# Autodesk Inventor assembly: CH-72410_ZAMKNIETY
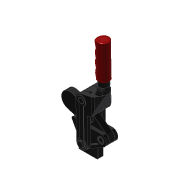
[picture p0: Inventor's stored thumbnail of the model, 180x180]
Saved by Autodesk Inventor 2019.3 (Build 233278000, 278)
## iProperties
Company: Î¢ÈíÖÐ¹ú
Created: 2012-10
Part Number: CH-72410_ZAMKNIETY
Material: Ogólny
Description: STEP AP203
Document SubType Name: Assembly
Designer: CADENGINEERING4
Stock Number: DOCISKI CIĘŻIE
Sending System: SolidWorks 2010
Preprocessor: SwSTEP 2.0
Title: CH-72410.STEP
Author: Î¢ÈíÓÃ»§
Revision Number: ÈÎºÎ
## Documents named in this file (13)
- D:\Vault_2016\Projekty\NASZ KATALOG\CLAMPTEK\STRONA\Heavy duty weldables\CH-72410\CH-72410_ZAMKNIETY.iam
- D:\Vault_2016\Projekty\NASZ KATALOG\CLAMPTEK\STRONA\Heavy duty weldables\CH-72410\72425-10.ipt
- D:\Vault_2016\Projekty\NASZ KATALOG\CLAMPTEK\STRONA\Heavy duty weldables\CH-72410\72425-06.ipt
- D:\Vault_2016\Projekty\NASZ KATALOG\CLAMPTEK\STRONA\Heavy duty weldables\CH-72410\M12.ipt
- D:\Vault_2016\Projekty\NASZ KATALOG\CLAMPTEK\STRONA\Heavy duty weldables\CH-72410\72425-07.ipt
- D:\Vault_2016\Projekty\NASZ KATALOG\CLAMPTEK\STRONA\Heavy duty weldables\CH-72410\CH-72410-03.ipt
- D:\Vault_2016\Projekty\NASZ KATALOG\CLAMPTEK\STRONA\Heavy duty weldables\CH-72410\72425-08.ipt
- D:\Vault_2016\Projekty\NASZ KATALOG\CLAMPTEK\STRONA\Heavy duty weldables\CH-72410\72425-11.ipt
- D:\Vault_2016\Projekty\NASZ KATALOG\CLAMPTEK\STRONA\Heavy duty weldables\CH-72410\CH-72410-01.ipt
- D:\Vault_2016\Projekty\NASZ KATALOG\CLAMPTEK\STRONA\Heavy duty weldables\CH-72410\CH-72410-02-02.ipt
- D:\Vault_2016\Projekty\NASZ KATALOG\CLAMPTEK\STRONA\Heavy duty weldables\CH-72410\CH-72410-02.ipt
- D:\Vault_2016\Projekty\NASZ KATALOG\CLAMPTEK\STRONA\Heavy duty weldables\CH-72410\72425-04.ipt
- D:\Vault_2016\Projekty\NASZ KATALOG\CLAMPTEK\STRONA\Heavy duty weldables\CH-72410\72425-03.ipt
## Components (23 placed, 23 different names)
1. 72425-10_1
2. 72425-06_2
3. M12_3
4. 72425-06_4
5. 72425-06_5
6. 72425-07_6
7. 72425-06_7
8. CH-72410-03_8
9. 72425-06_9
10. 72425-08_10
11. 72425-11_11 — Zestawiające:48, Zestawiające:49
12. CH-72410-01_12
13. 72425-08_13
14. CH-72410-02-02_14
15. 72425-06_15
16. 72425-06_16
17. CH-72410-02_17
18. 72425-06_18
19. 72425-06_19
20. 72425-06_20
21. 72425-04_21 — Zestawiające:48, Zestawiające:49
22. 72425-03_22
23. 72425-03_23
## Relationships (2: Mate 2)
- Zestawiające:48 [Mate]: 72425-11_11 ↔ 72425-04_21
- Zestawiające:49 [Mate]: 72425-11_11 ↔ 72425-04_21
